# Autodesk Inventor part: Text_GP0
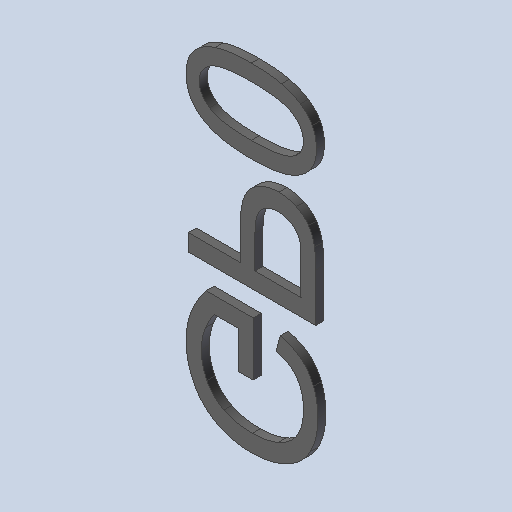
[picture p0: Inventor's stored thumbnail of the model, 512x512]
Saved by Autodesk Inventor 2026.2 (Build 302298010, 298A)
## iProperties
Created: 2026-10
Part Number: Text_GP0
Material: Générique
Document SubType Name: Modeling
Designer: mel
Density: 1 g/cm^3
Appearance: Par défaut
Author: mel
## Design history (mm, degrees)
feature "Base1"
feature "Base2"
feature "Base3"
node "Solide1"
node "Solide2"
node "Solide3"
